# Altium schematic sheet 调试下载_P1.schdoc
size 297 x 209 mm; Symbol: Drawing-Symbol_A4; Company: 嘉立创EDA; Version: V1.0; Page Size: A4; @Project Name: 水墨屏demo1; @Page Count: 1; @Update Date: 2026-02-28; @Create Date: 2026-02-28; @Schematic Name: Schematic1; @Page No: 1; @Page Name: P1; Device: Drawing-Symbol_A4; @Board Name: Board1; @Create Time: 16:32:38; @Update Time: 16:32:38; @Assembly Variant: Basic; Border: 1; Title Block Position: 3; Size: A4; Width: 1170; Height: 825; Region Start: 1; X Region Count: 6; Y Region Count: 4; Blade Width: 10
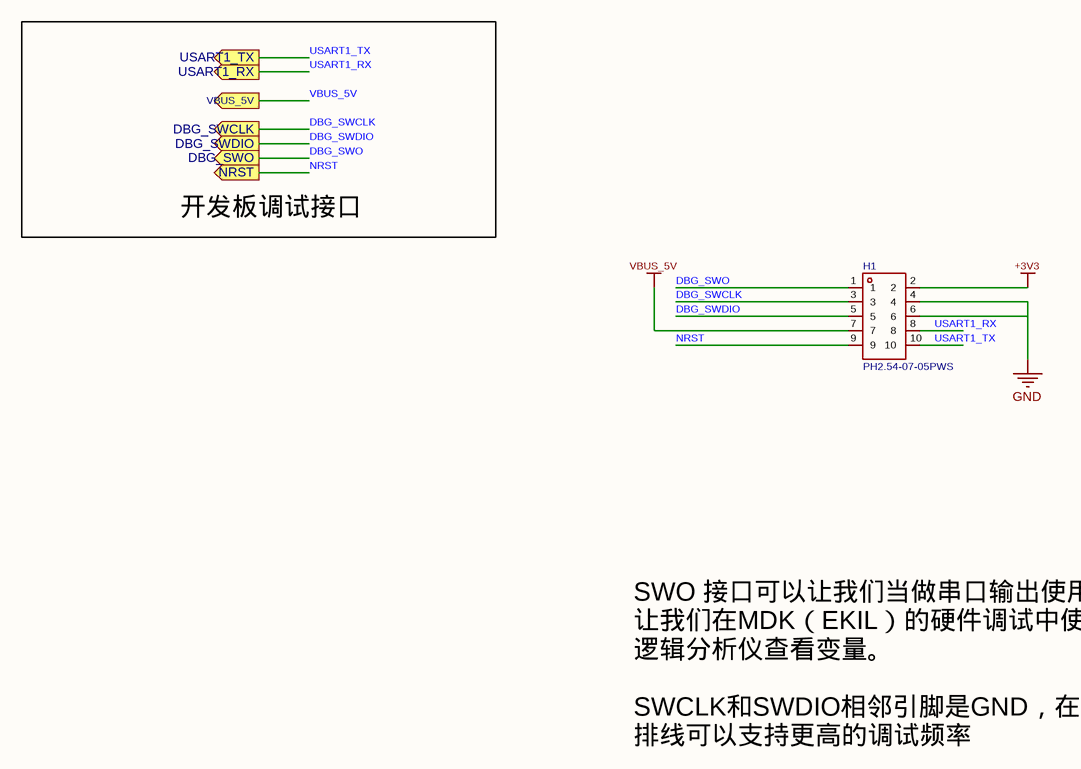
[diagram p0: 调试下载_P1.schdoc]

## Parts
H1  PH2.54-07-05PWS  [HDR-TH_10P-P2.54-H-M-R2-C5-S2.54-W12.9]

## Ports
DBG_SWCLK (out), DBG_SWDIO (out), DBG_SWO (out), NRST (out), USART1_RX (out), USART1_TX (out), VBUS_5V (out)

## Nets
+3V3: H1.2
GND: H1.4 H1.6
VBUS_5V: H1.7 ; port VBUS_5V
DBG_SWCLK: H1.3 ; port DBG_SWCLK
DBG_SWDIO: H1.5 ; port DBG_SWDIO
DBG_SWO: H1.1 ; port DBG_SWO
NRST: H1.9 ; port NRST
USART1_RX: H1.8 ; port USART1_RX
USART1_TX: H1.10 ; port USART1_TX

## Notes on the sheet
- 开发板调试接口
- SWO 接口可以让我们当做串口输出使用，也可以
  让我们在MDK（EKIL）的硬件调试中使用里面的
  逻辑分析仪查看变量。
  SWCLK和SWDIO相邻引脚是GND，在调试时使用双
  排线可以支持更高的调试频率

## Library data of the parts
H1 = PH2.54-07-05PWS: 插针结构:2x5P;间距:2.54mm;行距:2.54mm;圆针/方针:方针;安装方式:弯插;排数:双排;总PIN位数:10P;额定电流:3A;配合针长度:6mm;塑高:2.5mm;端接针长度:3mm;触头材质:黄铜;触头镀层:金;工作温度:-40℃~+105℃;颜色:黑色;; Manufacturer: XUNPU(讯普); AddInBom: yes; ModelId: 6c1aec56ddd942cfbfc785a4f1a9930e0819f05c4eef4c71ace90d822a990e87; ModelTransform: 492.16437,507.873,0,0,0,0,0,-190.945,-118.11; Pin Structure: 2x5P; Pitch: 2.54mm; Circluar Pins/Square Pins: 方针; Current Rating: 3A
